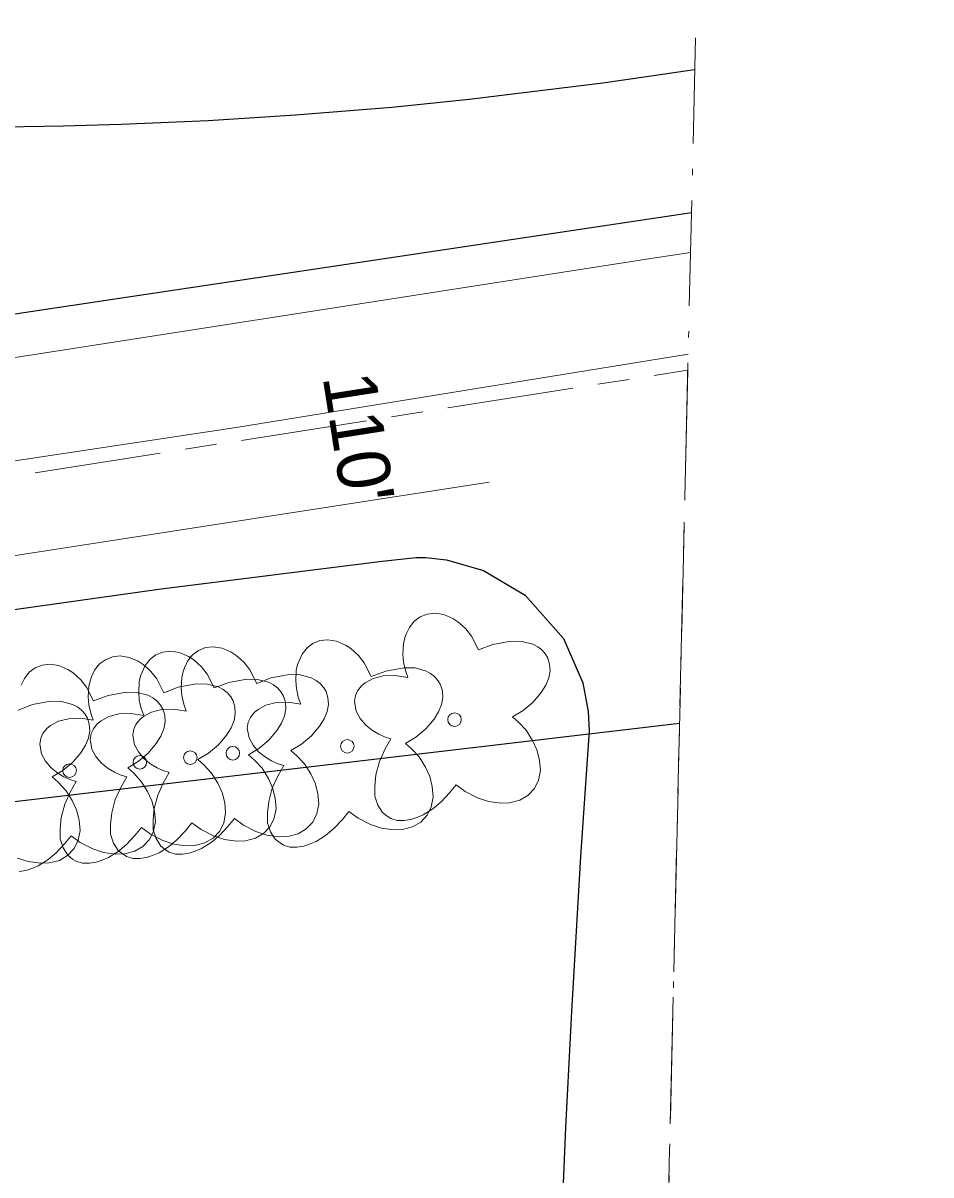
# Model space of a CAD drawing. Extents: x -861682 to -858969, y -1797841 to -1795153.
# Drawn here: x -859077.7 to -858974.4, y -1796475.1 to -1796344.2 of the extents above; entities that cross this region are included whole.
import ezdxf

# ---------------------------------------------------------------- set-up
doc = ezdxf.new("R2010")
doc.units = 0
doc.header["$LTSCALE"] = 2.4
doc.linetypes.add('DOT_DASHED', pattern=[7.7, 5, -1.2, 0.3, -1.2])
doc.linetypes.add('LONG_DASH_SHORT_DASH', pattern=[9.9, 6, -1.2, 1.5, -1.2])
for name, color, linetype, lineweight in [('10', 7, 'Continuous', 25), ('17', 7, 'Continuous', 13), ('32', 7, 'LONG_DASH_SHORT_DASH', 13), ('42', 7, 'Continuous', 25), ('54', 7, 'Continuous', 13), ('61', 7, 'Continuous', 13)]:
    doc.layers.add(name, color=color, linetype=linetype, lineweight=lineweight)
doc.layers.add('43', color=7, linetype='Continuous')

msp = doc.modelspace()

# ---------------------------------------------------------------- linework, layer by layer
at = {"layer": '10'}
for points in [[(-859006.787, -1796350.274), (-859001.839, -1796349.548), (-859001.287, -1796349.467)], [(-859135.862, -1796353.628), (-859124.882, -1796354.552), (-859114.984, -1796355.192), (-859106.178, -1796355.607), (-859098.468, -1796355.852), (-859092.959, -1796355.96), (-859088.552, -1796356.005), (-859085.246, -1796356.015), (-859083.042, -1796356.011), (-859079.736, -1796355.988), (-859073.125, -1796355.88), (-859066.515, -1796355.691), (-859056.607, -1796355.255), (-859046.708, -1796354.637), (-859035.725, -1796353.737), (-859026.954, -1796352.855), (-859011.736, -1796350.979), (-859006.787, -1796350.274)], [(-859311.205, -1796413.342), (-859217.078, -1796397.962), (-859001.666, -1796365.735)], [(-859036.837, -1796405.355), (-859032.969, -1796404.936), (-859031.867, -1796404.958), (-859029.526, -1796405.213), (-859025.302, -1796406.438), (-859020.581, -1796409.244), (-859016.223, -1796414.174), (-859014.018, -1796419.204), (-859013.403, -1796422.448), (-859013.302, -1796424.649)], [(-859155.845, -1796423.511), (-859150.929, -1796422.601), (-859144.722, -1796421.471), (-859115.398, -1796416.434), (-859088.176, -1796412.198), (-859061.985, -1796408.521), (-859036.837, -1796405.355)], [(-859013.302, -1796424.649), (-859014.282, -1796438.941), (-859015.325, -1796456.542), (-859015.99, -1796469.749), (-859016.637, -1796485.163), (-859016.98, -1796495.076), (-859017.405, -1796510.707), (-859017.51, -1796515.705)]]:
    msp.add_lwpolyline(points, dxfattribs=at)
at = {"layer": '17'}
for points in [[(-859028.429, -1796430.79), (-859027.387, -1796431.558), (-859025.981, -1796432.28), (-859024.733, -1796432.686), (-859023.361, -1796432.882), (-859022.343, -1796432.832), (-859021.199, -1796432.542), (-859020.267, -1796431.99), (-859019.527, -1796431.202), (-859019.059, -1796430.244), (-859018.849, -1796429.166), (-859018.953, -1796427.97), (-859019.243, -1796426.798), (-859019.729, -1796425.738), (-859020.451, -1796424.594), (-859021.317, -1796423.674), (-859021.999, -1796423.062), (-859020.817, -1796422.346), (-859019.671, -1796421.398), (-859018.751, -1796420.306), (-859018.229, -1796419.45), (-859017.897, -1796418.636), (-859017.751, -1796417.82), (-859017.791, -1796417.058), (-859018.007, -1796416.378), (-859018.265, -1796415.926), (-859018.685, -1796415.452), (-859019.145, -1796415.098), (-859019.711, -1796414.808), (-859020.947, -1796414.48), (-859022.189, -1796414.446), (-859024.235, -1796414.822), (-859025.895, -1796415.46), (-859026.685, -1796413.882), (-859027.339, -1796413.068), (-859027.751, -1796412.666), (-859028.215, -1796412.266), (-859028.817, -1796411.874), (-859029.821, -1796411.442), (-859030.835, -1796411.272), (-859031.723, -1796411.372), (-859032.523, -1796411.706), (-859033.189, -1796412.192), (-859033.749, -1796412.898), (-859034.099, -1796413.654), (-859034.257, -1796414.092), (-859034.425, -1796414.768), (-859034.477, -1796415.93), (-859034.405, -1796416.828), (-859034.193, -1796417.79), (-859033.909, -1796418.596), (-859035.351, -1796418.364), (-859036.709, -1796418.414), (-859037.867, -1796418.7), (-859038.755, -1796419.198), (-859039.195, -1796419.542), (-859039.629, -1796420.108), (-859039.867, -1796420.642), (-859039.991, -1796421.32), (-859039.789, -1796422.424), (-859039.333, -1796423.236), (-859038.709, -1796423.998), (-859037.931, -1796424.614), (-859037.233, -1796425.038), (-859036.569, -1796425.326), (-859035.841, -1796425.564), (-859036.525, -1796426.776), (-859037.147, -1796428.144), (-859037.543, -1796429.646), (-859037.677, -1796430.98), (-859037.667, -1796432.07), (-859037.333, -1796433.088), (-859036.811, -1796433.934), (-859036.253, -1796434.37), (-859035.867, -1796434.616), (-859035.133, -1796434.84), (-859034.339, -1796434.852), (-859033.569, -1796434.728), (-859032.909, -1796434.516), (-859032.165, -1796434.194), (-859031.089, -1796433.514), (-859030.127, -1796432.728), (-859029.171, -1796431.71), (-859028.425, -1796430.8)], [(-859040.622, -1796433.82), (-859039.58, -1796434.588), (-859038.174, -1796435.31), (-859036.926, -1796435.716), (-859035.554, -1796435.912), (-859034.536, -1796435.862), (-859033.392, -1796435.572), (-859032.46, -1796435.02), (-859031.72, -1796434.232), (-859031.252, -1796433.274), (-859031.042, -1796432.196), (-859031.146, -1796431), (-859031.436, -1796429.828), (-859031.922, -1796428.768), (-859032.644, -1796427.624), (-859033.51, -1796426.704), (-859034.192, -1796426.092), (-859033.01, -1796425.376), (-859031.864, -1796424.428), (-859030.944, -1796423.336), (-859030.422, -1796422.48), (-859030.09, -1796421.666), (-859029.944, -1796420.85), (-859029.984, -1796420.088), (-859030.2, -1796419.408), (-859030.458, -1796418.956), (-859030.878, -1796418.482), (-859031.338, -1796418.128), (-859031.904, -1796417.838), (-859033.14, -1796417.51), (-859034.382, -1796417.476), (-859036.428, -1796417.852), (-859038.088, -1796418.49), (-859038.878, -1796416.912), (-859039.532, -1796416.098), (-859039.944, -1796415.696), (-859040.408, -1796415.296), (-859041.01, -1796414.904), (-859042.014, -1796414.472), (-859043.028, -1796414.302), (-859043.916, -1796414.402), (-859044.716, -1796414.736), (-859045.382, -1796415.222), (-859045.942, -1796415.928), (-859046.292, -1796416.684), (-859046.45, -1796417.122), (-859046.618, -1796417.798), (-859046.67, -1796418.96), (-859046.598, -1796419.858), (-859046.386, -1796420.82), (-859046.102, -1796421.626), (-859047.544, -1796421.394), (-859048.902, -1796421.444), (-859050.06, -1796421.73), (-859050.948, -1796422.228), (-859051.388, -1796422.572), (-859051.822, -1796423.138), (-859052.06, -1796423.672), (-859052.184, -1796424.35), (-859051.982, -1796425.454), (-859051.526, -1796426.266), (-859050.902, -1796427.028), (-859050.124, -1796427.644), (-859049.426, -1796428.068), (-859048.762, -1796428.356), (-859048.034, -1796428.594), (-859048.718, -1796429.806), (-859049.34, -1796431.174), (-859049.736, -1796432.676), (-859049.87, -1796434.01), (-859049.86, -1796435.1), (-859049.526, -1796436.118), (-859049.004, -1796436.964), (-859048.446, -1796437.4), (-859048.06, -1796437.646), (-859047.326, -1796437.87), (-859046.532, -1796437.882), (-859045.762, -1796437.758), (-859045.102, -1796437.546), (-859044.358, -1796437.224), (-859043.282, -1796436.544), (-859042.32, -1796435.758), (-859041.364, -1796434.74), (-859040.618, -1796433.83)], [(-859058.48, -1796435.11), (-859057.438, -1796435.878), (-859056.032, -1796436.6), (-859054.784, -1796437.006), (-859053.412, -1796437.202), (-859052.394, -1796437.152), (-859051.25, -1796436.862), (-859050.318, -1796436.31), (-859049.578, -1796435.522), (-859049.11, -1796434.564), (-859048.9, -1796433.486), (-859049.004, -1796432.29), (-859049.294, -1796431.118), (-859049.78, -1796430.058), (-859050.502, -1796428.914), (-859051.368, -1796427.994), (-859052.05, -1796427.382), (-859050.868, -1796426.666), (-859049.722, -1796425.718), (-859048.802, -1796424.626), (-859048.28, -1796423.77), (-859047.948, -1796422.956), (-859047.802, -1796422.14), (-859047.842, -1796421.378), (-859048.058, -1796420.698), (-859048.316, -1796420.246), (-859048.736, -1796419.772), (-859049.196, -1796419.418), (-859049.762, -1796419.128), (-859050.998, -1796418.8), (-859052.24, -1796418.766), (-859054.286, -1796419.142), (-859055.946, -1796419.78), (-859056.736, -1796418.202), (-859057.39, -1796417.388), (-859057.802, -1796416.986), (-859058.266, -1796416.586), (-859058.868, -1796416.194), (-859059.872, -1796415.762), (-859060.886, -1796415.592), (-859061.774, -1796415.692), (-859062.574, -1796416.026), (-859063.24, -1796416.512), (-859063.8, -1796417.218), (-859064.15, -1796417.974), (-859064.308, -1796418.412), (-859064.476, -1796419.088), (-859064.528, -1796420.25), (-859064.456, -1796421.148), (-859064.244, -1796422.11), (-859063.96, -1796422.916), (-859065.402, -1796422.684), (-859066.76, -1796422.734), (-859067.918, -1796423.02), (-859068.806, -1796423.518), (-859069.246, -1796423.862), (-859069.68, -1796424.428), (-859069.918, -1796424.962), (-859070.042, -1796425.64), (-859069.84, -1796426.744), (-859069.384, -1796427.556), (-859068.76, -1796428.318), (-859067.982, -1796428.934), (-859067.284, -1796429.358), (-859066.62, -1796429.646), (-859065.892, -1796429.884), (-859066.576, -1796431.096), (-859067.198, -1796432.464), (-859067.594, -1796433.966), (-859067.728, -1796435.3), (-859067.718, -1796436.39), (-859067.384, -1796437.408), (-859066.862, -1796438.254), (-859066.304, -1796438.69), (-859065.918, -1796438.936), (-859065.184, -1796439.16), (-859064.39, -1796439.172), (-859063.62, -1796439.048), (-859062.96, -1796438.836), (-859062.216, -1796438.514), (-859061.14, -1796437.834), (-859060.178, -1796437.048), (-859059.222, -1796436.03), (-859058.476, -1796435.12)], [(-859053.638, -1796434.611), (-859052.596, -1796435.379), (-859051.19, -1796436.101), (-859049.942, -1796436.507), (-859048.57, -1796436.703), (-859047.552, -1796436.653), (-859046.408, -1796436.363), (-859045.476, -1796435.811), (-859044.736, -1796435.023), (-859044.268, -1796434.065), (-859044.058, -1796432.987), (-859044.162, -1796431.791), (-859044.452, -1796430.619), (-859044.938, -1796429.559), (-859045.66, -1796428.415), (-859046.526, -1796427.495), (-859047.208, -1796426.883), (-859046.026, -1796426.167), (-859044.88, -1796425.219), (-859043.96, -1796424.127), (-859043.438, -1796423.271), (-859043.106, -1796422.457), (-859042.96, -1796421.641), (-859043, -1796420.879), (-859043.216, -1796420.199), (-859043.474, -1796419.747), (-859043.894, -1796419.273), (-859044.354, -1796418.919), (-859044.92, -1796418.629), (-859046.156, -1796418.301), (-859047.398, -1796418.267), (-859049.444, -1796418.643), (-859051.104, -1796419.281), (-859051.894, -1796417.703), (-859052.548, -1796416.889), (-859052.96, -1796416.487), (-859053.424, -1796416.087), (-859054.026, -1796415.695), (-859055.03, -1796415.263), (-859056.044, -1796415.093), (-859056.932, -1796415.193), (-859057.732, -1796415.527), (-859058.398, -1796416.013), (-859058.958, -1796416.719), (-859059.308, -1796417.475), (-859059.466, -1796417.913), (-859059.634, -1796418.589), (-859059.686, -1796419.751), (-859059.614, -1796420.649), (-859059.402, -1796421.611), (-859059.118, -1796422.417), (-859060.56, -1796422.185), (-859061.918, -1796422.235), (-859063.076, -1796422.521), (-859063.964, -1796423.019), (-859064.404, -1796423.363), (-859064.838, -1796423.929), (-859065.076, -1796424.463), (-859065.2, -1796425.141), (-859064.998, -1796426.245), (-859064.542, -1796427.057), (-859063.918, -1796427.819), (-859063.14, -1796428.435), (-859062.442, -1796428.859), (-859061.778, -1796429.147), (-859061.05, -1796429.385), (-859061.734, -1796430.597), (-859062.356, -1796431.965), (-859062.752, -1796433.467), (-859062.886, -1796434.801), (-859062.876, -1796435.891), (-859062.542, -1796436.909), (-859062.02, -1796437.755), (-859061.462, -1796438.191), (-859061.076, -1796438.437), (-859060.342, -1796438.661), (-859059.548, -1796438.673), (-859058.778, -1796438.549), (-859058.118, -1796438.337), (-859057.374, -1796438.015), (-859056.298, -1796437.335), (-859055.336, -1796436.549), (-859054.38, -1796435.531), (-859053.634, -1796434.621)], [(-859064.217, -1796435.648), (-859063.175, -1796436.416), (-859061.769, -1796437.138), (-859060.521, -1796437.544), (-859059.149, -1796437.74), (-859058.131, -1796437.69), (-859056.987, -1796437.4), (-859056.055, -1796436.848), (-859055.315, -1796436.06), (-859054.847, -1796435.102), (-859054.637, -1796434.024), (-859054.741, -1796432.828), (-859055.031, -1796431.656), (-859055.517, -1796430.596), (-859056.239, -1796429.452), (-859057.105, -1796428.532), (-859057.787, -1796427.92), (-859056.605, -1796427.204), (-859055.459, -1796426.256), (-859054.539, -1796425.164), (-859054.017, -1796424.308), (-859053.685, -1796423.494), (-859053.539, -1796422.678), (-859053.579, -1796421.916), (-859053.795, -1796421.236), (-859054.053, -1796420.784), (-859054.473, -1796420.31), (-859054.933, -1796419.956), (-859055.499, -1796419.666), (-859056.735, -1796419.338), (-859057.977, -1796419.304), (-859060.023, -1796419.68), (-859061.683, -1796420.318), (-859062.473, -1796418.74), (-859063.127, -1796417.926), (-859063.539, -1796417.524), (-859064.003, -1796417.124), (-859064.605, -1796416.732), (-859065.609, -1796416.3), (-859066.623, -1796416.13), (-859067.511, -1796416.23), (-859068.311, -1796416.564), (-859068.977, -1796417.05), (-859069.537, -1796417.756), (-859069.887, -1796418.512), (-859070.045, -1796418.95), (-859070.213, -1796419.626), (-859070.265, -1796420.788), (-859070.193, -1796421.686), (-859069.981, -1796422.648), (-859069.697, -1796423.454), (-859071.139, -1796423.222), (-859072.497, -1796423.272), (-859073.655, -1796423.558), (-859074.543, -1796424.056), (-859074.983, -1796424.4), (-859075.417, -1796424.966), (-859075.655, -1796425.5), (-859075.779, -1796426.178), (-859075.577, -1796427.282), (-859075.121, -1796428.094), (-859074.497, -1796428.856), (-859073.719, -1796429.472), (-859073.021, -1796429.896), (-859072.357, -1796430.184), (-859071.629, -1796430.422), (-859072.313, -1796431.634), (-859072.935, -1796433.002), (-859073.331, -1796434.504), (-859073.465, -1796435.838), (-859073.455, -1796436.928), (-859073.121, -1796437.946), (-859072.599, -1796438.792), (-859072.041, -1796439.228), (-859071.655, -1796439.474), (-859070.921, -1796439.698), (-859070.127, -1796439.71), (-859069.357, -1796439.586), (-859068.697, -1796439.374), (-859067.953, -1796439.052), (-859066.877, -1796438.372), (-859065.915, -1796437.586), (-859064.959, -1796436.568), (-859064.213, -1796435.658)], [(-859072.208, -1796436.59), (-859071.166, -1796437.358), (-859069.76, -1796438.08), (-859068.512, -1796438.486), (-859067.14, -1796438.682), (-859066.122, -1796438.632), (-859064.978, -1796438.342), (-859064.046, -1796437.79), (-859063.306, -1796437.002), (-859062.838, -1796436.044), (-859062.628, -1796434.966), (-859062.732, -1796433.77), (-859063.022, -1796432.598), (-859063.508, -1796431.538), (-859064.23, -1796430.394), (-859065.096, -1796429.474), (-859065.778, -1796428.862), (-859064.596, -1796428.146), (-859063.45, -1796427.198), (-859062.53, -1796426.106), (-859062.008, -1796425.25), (-859061.676, -1796424.436), (-859061.53, -1796423.62), (-859061.57, -1796422.858), (-859061.786, -1796422.178), (-859062.044, -1796421.726), (-859062.464, -1796421.252), (-859062.924, -1796420.898), (-859063.49, -1796420.608), (-859064.726, -1796420.28), (-859065.968, -1796420.246), (-859068.014, -1796420.622), (-859069.674, -1796421.26), (-859070.464, -1796419.682), (-859071.118, -1796418.868), (-859071.53, -1796418.466), (-859071.994, -1796418.066), (-859072.596, -1796417.674), (-859073.6, -1796417.242), (-859074.614, -1796417.072), (-859075.502, -1796417.172), (-859076.302, -1796417.506), (-859076.968, -1796417.992), (-859077.528, -1796418.698), (-859077.878, -1796419.454)], [(-859078.331, -1796439.113), (-859077.083, -1796439.519), (-859075.711, -1796439.715), (-859074.693, -1796439.665), (-859073.549, -1796439.375), (-859072.617, -1796438.823), (-859071.877, -1796438.035), (-859071.409, -1796437.077), (-859071.199, -1796435.999), (-859071.303, -1796434.803), (-859071.593, -1796433.631), (-859072.079, -1796432.571), (-859072.801, -1796431.427), (-859073.667, -1796430.507), (-859074.349, -1796429.895), (-859073.167, -1796429.179), (-859072.021, -1796428.231), (-859071.101, -1796427.139), (-859070.579, -1796426.283), (-859070.247, -1796425.469), (-859070.101, -1796424.653), (-859070.141, -1796423.891), (-859070.357, -1796423.211), (-859070.615, -1796422.759), (-859071.035, -1796422.285), (-859071.495, -1796421.931), (-859072.061, -1796421.641), (-859073.297, -1796421.313), (-859074.539, -1796421.279), (-859076.585, -1796421.655), (-859078.245, -1796422.293)], [(-859078.118, -1796440.652), (-859077.348, -1796440.528), (-859076.688, -1796440.316), (-859075.944, -1796439.994), (-859074.868, -1796439.314), (-859073.906, -1796438.528), (-859072.95, -1796437.51), (-859072.204, -1796436.6)]]:
    msp.add_lwpolyline(points, dxfattribs=at)
for centre in [(-859028.609, -1796423.378), (-859040.802, -1796426.408), (-859058.66, -1796427.698), (-859053.818, -1796427.199), (-859072.388, -1796429.178), (-859064.397, -1796428.236)]:
    msp.add_circle(centre, 0.773, dxfattribs=at)
at = {"layer": '32'}
msp.add_line((-859002.083, -1796383.657), (-859035.9, -1797835.881), dxfattribs=at)
msp.add_lwpolyline([(-861651.105, -1796687.844), (-861333.558, -1796608.31), (-860734.009, -1796456.297), (-860402.78, -1796372.876), (-860279.286, -1796339.345), (-860213.04, -1796323.806), (-860166.423, -1796315.627), (-860126.348, -1796310.72), (-860089.545, -1796308.267), (-860056.831, -1796312.356), (-859995.492, -1796331.984), (-859827.834, -1796395.777), (-859764.042, -1796414.588), (-859688.8, -1796435.852), (-859629.915, -1796444.03), (-859562.034, -1796449.756), (-859471.253, -1796448.938), (-859395.193, -1796443.213), (-859240.62, -1796421.131), (-859002.083, -1796383.657)], dxfattribs=at)
at = {"layer": '42'}
msp.add_line((-859003.018, -1796423.81), (-859104.779, -1796435.814), dxfattribs=at)
at = {"layer": '54'}
for points in [[(-859316.098, -1796418.873), (-859280.993, -1796413.366), (-859244.156, -1796407.091), (-859200.197, -1796400.735), (-859142.824, -1796391.754), (-859077.601, -1796382.042), (-859005.778, -1796370.863), (-859001.771, -1796370.264)], [(-859002.041, -1796381.842), (-859053.45, -1796390.181), (-859156.868, -1796405.745), (-859244.786, -1796419.699), (-859343.381, -1796434.293), (-859400.907, -1796442.299), (-859441.496, -1796446.496), (-859486.409, -1796447.753), (-859546.168, -1796448.733)], [(-859024.666, -1796396.369), (-859086.63, -1796405.988), (-859154.426, -1796417.212), (-859225.106, -1796428.135), (-859296.827, -1796439.137), (-859350.437, -1796446.328), (-859398.709, -1796453.199), (-859433.489, -1796457.311), (-859461.242, -1796459.332), (-859512.74, -1796459.733), (-859545.87, -1796459.101)]]:
    msp.add_lwpolyline(points, dxfattribs=at)
at = {"layer": '61', "linetype": 'DOT_DASHED'}
msp.add_line((-859035.9, -1797835.881), (-858974.429, -1795196.105), dxfattribs=at)

# ---------------------------------------------------------------- texts
at = {"layer": '43'}
msp.add_text("110'", height=6, rotation=278.9, dxfattribs=at).set_placement((-859043.621, -1796384.409))

doc.saveas('drawing.dxf')
